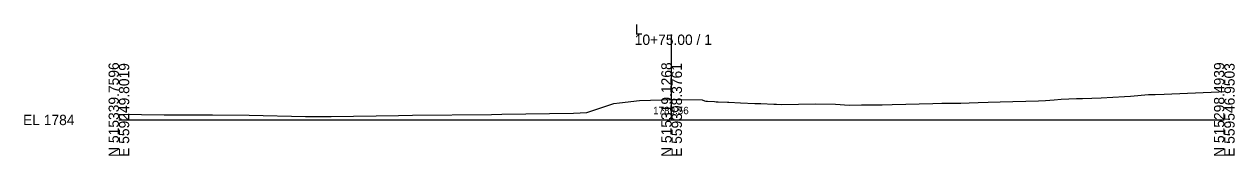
# Model space of a CAD drawing. Extents: x -26 to 1303, y -10 to 9545.
# Drawn here: x -25.7 to 302.8, y 1490.3 to 1525.9 of the extents above; entities that cross this region are included whole.
import ezdxf

# ---------------------------------------------------------------- set-up
doc = ezdxf.new("R2010")
doc.units = 0
for name, color, linetype in [('Exist Cross Section Cell', 7, 'Continuous'), ('Exist XS Center Line Elevation Label', 7, 'Continuous'), ('Exist XS Ground Line', 7, 'Continuous')]:
    doc.layers.add(name, color=color, linetype=linetype)

msp = doc.modelspace()

# ---------------------------------------------------------------- linework, layer by layer
at = {"layer": 'Exist Cross Section Cell'}
for p, q in [((150, 1500), (150, 1523.13)), ((0, 1500), (150, 1500)), ((150, 1500), (300, 1500))]:
    msp.add_line(p, q, dxfattribs=at)
at = {"layer": 'Exist XS Ground Line'}
for p, q in [((135.85, 1504.67), (141.3, 1505.25)), ((141.3, 1505.25), (147.26, 1505.46)), ((147.26, 1505.46), (150.06, 1505.57)), ((150.06, 1505.57), (152.7, 1505.5)), ((152.7, 1505.5), (158.33, 1505.44)), ((158.33, 1505.44), (158.95, 1505.2)), ((158.95, 1505.2), (159.32, 1505.13)), ((159.32, 1505.13), (159.78, 1505.06)), ((159.78, 1505.06), (161.65, 1504.97)), ((161.65, 1504.97), (162.09, 1504.93)), ((162.09, 1504.93), (162.6, 1504.91)), ((162.6, 1504.91), (165.14, 1504.8)), ((165.14, 1504.8), (165.57, 1504.8)), ((165.57, 1504.8), (168.68, 1504.66)), ((230.75, 1504.63), (233.2, 1504.69)), ((233.2, 1504.69), (235.93, 1504.78)), ((235.93, 1504.78), (239.13, 1504.9)), ((239.13, 1504.9), (249.61, 1505.16)), ((249.61, 1505.16), (251.43, 1505.27)), ((251.43, 1505.27), (253.81, 1505.44)), ((253.81, 1505.44), (255.68, 1505.6)), ((255.68, 1505.6), (259.87, 1505.81)), ((259.87, 1505.81), (261.11, 1505.84)), ((261.11, 1505.84), (261.5, 1505.84)), ((261.5, 1505.84), (266.58, 1506.01)), ((266.58, 1506.01), (269.77, 1506.22)), ((269.77, 1506.22), (272.91, 1506.38)), ((272.91, 1506.38), (274.58, 1506.48)), ((274.58, 1506.48), (279.44, 1506.87)), ((279.44, 1506.87), (281.25, 1506.92)), ((281.25, 1506.92), (283.7, 1506.98)), ((283.7, 1506.98), (298.52, 1507.65)), ((298.52, 1507.65), (300, 1507.71)), ((0, 1501.56), (12.26, 1501.38)), ((12.26, 1501.38), (25.41, 1501.43)), ((25.41, 1501.43), (35.34, 1501.29)), ((79.72, 1501.3), (101.16, 1501.51)), ((101.16, 1501.51), (103.94, 1501.55)), ((103.94, 1501.55), (123.42, 1501.81)), ((123.42, 1501.81), (127.01, 1501.98)), ((127.01, 1501.98), (131.09, 1503.42)), ((131.09, 1503.42), (134.36, 1504.5)), ((134.36, 1504.5), (135.85, 1504.67)), ((168.68, 1504.66), (172.63, 1504.49)), ((172.63, 1504.49), (174.21, 1504.42)), ((174.21, 1504.42), (177.74, 1504.28)), ((177.74, 1504.28), (178.43, 1504.26)), ((178.43, 1504.26), (179.93, 1504.2)), ((179.93, 1504.2), (188.98, 1504.36)), ((188.98, 1504.36), (194.49, 1504.29)), ((194.49, 1504.29), (198.16, 1503.99)), ((198.16, 1503.99), (201.49, 1504.13)), ((201.49, 1504.13), (204.41, 1504.11)), ((204.41, 1504.11), (207.17, 1504.14)), ((207.17, 1504.14), (209.84, 1504.2)), ((209.84, 1504.2), (220.93, 1504.45)), ((220.93, 1504.45), (223.32, 1504.54)), ((223.32, 1504.54), (223.92, 1504.56)), ((223.92, 1504.56), (226.21, 1504.57)), ((226.21, 1504.57), (228.45, 1504.59)), ((228.45, 1504.59), (230.75, 1504.63)), ((35.34, 1501.29), (50.67, 1500.91)), ((50.67, 1500.91), (57.57, 1500.96)), ((57.57, 1500.96), (75.91, 1501.25)), ((75.91, 1501.25), (79.72, 1501.3))]:
    msp.add_line(p, q, dxfattribs=at)

# ---------------------------------------------------------------- texts
at = {"layer": 'Exist Cross Section Cell'}
for s, p in [('L', (140, 1523.13)), ('10+75.00 / 1', (140, 1520.33)), ('EL 1784', (-26, 1498.6))]:
    msp.add_text(s, height=2.8, dxfattribs=at).set_placement(p)
for s, p in [('N 515339.7596', (0, 1490)), ('E 559249.8019', (2.8, 1490)), ('N 515319.1268', (150, 1490)), ('E 559398.3761', (152.8, 1490)), ('N 515298.4939', (300, 1490)), ('E 559546.9503', (302.8, 1490))]:
    msp.add_text(s, height=2.8, rotation=90, dxfattribs=at).set_placement(p)
at = {"layer": 'Exist XS Center Line Elevation Label'}
msp.add_text('1789.56', height=2, dxfattribs=at).set_placement((144.98, 1501.56))

doc.saveas('drawing.dxf')
